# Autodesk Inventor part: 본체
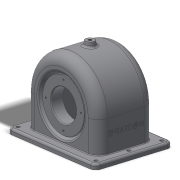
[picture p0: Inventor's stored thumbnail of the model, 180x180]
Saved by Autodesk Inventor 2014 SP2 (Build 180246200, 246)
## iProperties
Created: 2015-09
Part Number: 본체
Material: 일반
Document SubType Name: Modeling
Designer: 201-20
Density: 1 g/cm^3
Appearance: 기본값
Author: 201-20
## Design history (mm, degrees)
sketch "스케치6"
  geometry: L1 (-70, -40)-(70, -40); L2 (70, -40)-(70, -47); L3 (70, -47)-(-70, -47); L4 (-70, -47)-(-70, -40); 2 further points
  constraints: 8 end point, 2 parallel, 1 horizontal, 1 midpoint, 1 perpendicular, 1 vertical alignment
  dimensions: "d2" = 140 distance of L2.end L3.end; "d3" = 7 distance between parallel lines of L1 L3; "d4" = 47 distance from line of L3 point (0, 0)
extrude "돌출2" new body sketch "스케치6" stored distance "d5" = 104; taper "d6" = 0 deg
sketch "스케치10"
  geometry: L1 (70, -40)-(-70, -40) reference; L2 (-57, 0)-(57, 0); L3 (57, 0)-(57, -40); L4 (-57, -40)-(-57, 0); L5 (70, -47)-(-70, -47) reference; L6 (-51, 0)-(-51, -40); L7 (51, 0)-(51, -40); L8 (57, -40)-(51, -40); L9 (-51, -40)-(-57, -40); L10 (-51, -40)-(51, -40); A1 r 57 centre (0, 0) between (57, 0) and (-57, 0); A2 r 51 centre (0, 0) between (51, 0) and (-51, 0); 2 further points
  constraints: 16 end point, 5 perpendicular, 4 parallel, 4 point on circle, 3 midpoint, 2 centre point, 2 tangent, 1 coincident, 1 horizontal, 1 point on line, 1 vertical alignment
  dimensions: "d20" = 47 distance between parallel lines of L2 L5; "d21" = 6 radial gap between concentric circles of A1 A2; "d110" = 51 radius of A2
extrude "돌출3" join sketch "스케치10" stored distance "d17" = 77; taper "d18" = 0 deg
extrude "돌출4" cut sketch "스케치10" stored distance "d22" = 67; taper "d23" = 0 deg
sketch "스케치14"
  geometry: L1 (19, -18.5)-(121, -18.5); L2 (121, -18.5)-(121, -85.5); L3 (121, -85.5)-(19, -85.5); L4 (19, -85.5)-(19, -18.5); 3 further points
  constraints: 8 end point, 2 midpoint, 2 parallel, 1 horizontal, 1 horizontal alignment, 1 perpendicular, 1 vertical alignment
  dimensions: "d24" = 67 distance of L1.end L2.end; "d25" = 102 distance of L1.start L1.end
extrude "돌출5" cut sketch "스케치14" distance "d26" = 20; taper "d27" = 0 deg
fillet "모깎기1" dims "d28" = 14
fillet "모깎기3" dims "d34" = 9
sketch "스케치15"
  geometry: L1 (57, 38.5)-(0, 38.5) reference; L2 (51, 33.5)-(0, 33.5) reference; L3 (39.747, 33.5)-(28, 19.5); L4 (28, 19.5)-(20, 19.5); L5 (20, 19.5)-(20, 35.5); L6 (33, 33.237)-(37.416, 38.5); L7 (33, 33.237)-(33, 35.5); L8 (33, 35.5)-(20, 35.5); L9 (37.416, 38.5)-(39.747, 33.5); L10 (37.416, 38.5)-(20, 38.5); L11 (20, 38.5)-(20, 35.5); L12 (0, -72.8)-(0, 72.8) reference; 1 further point
  constraints: 18 end point, 3 parallel, 3 perpendicular, 3 point on line
  dimensions: "d30" = 28 horizontal distance of L3.end point (0, 0); "d31" = 3 distance between parallel lines of L8 L1; "d32" = 16 distance of L4.end L5.end; "d33" = 50 deg angle of L4 L3; "d35" = 33 distance from line of L7 point (0, 0); "d37" = 5 distance between parallel lines of L3 L6; "d38" = 20 distance from line of L5 point (0, 0)
revolve "회전1" stored, may be unused: angle "d39" = 90 deg
revolve "회전2" stored, may be unused: angle "d40" = 90 deg
sketch "스케치17"
  geometry: C1 r 31 at (0, 0); C2 r 20 at (0, 0); 1 further point
  constraints: 2 centre point, 2 coincident
  dimensions: "d41" = 62 diameter of C1; "d42" = 40 diameter of C2
extrude "돌출6" join sketch "스케치17" distance "d43" = 10; taper "d44" = 0 deg
sketch "스케치18"
  geometry: C1 r 20 at (0, 0) reference; 1 further point
extrude "돌출7" cut sketch "스케치18" distance "d45" = 87; taper "d46" = 0 deg
node "작업 평면2"
sketch "스케치20"
  geometry: C1 r 6 at (70, -52); 1 further point
  constraints: 1 centre point, 1 coincident
  dimensions: "d48" = 12 diameter of C1
extrude "돌출8" join sketch "스케치20" stored distance "d49" = 7; taper "d50" = 10 deg
hole "구멍1" diameter "d53" = 4.459; stored, may be unused: countersink angle "d57" = 90 deg, drill point angle "d59" = 0 deg; dims "d54" = 30, "d55" = 4, "d56" = 2, "d58" = 30, "d60" = 10, "d61" = 10
fillet "모깎기4" dims "d62" = 7
sketch "스케치21"
  geometry: 2 further points
  dimensions: "d63" = 62 horizontal distance of point (1, 8) point (63, 52); "d64" = 44 vertical distance of point (1, 8) point (63, 52)
hole "구멍2" sketch "스케치21" at (1, 8) diameter "d65" = 5; stored, may be unused: countersink angle "d69" = 90 deg, drill point angle "d71" = 0 deg; dims "d66" = 10, "d67" = 4, "d68" = 2, "d70" = 10
fillet "모깎기5" dims "d75" = 3, "d76" = 3, "d77" = 3, "d78" = 1
sketch "스케치22"
  geometry: 2 further points
  constraints: 1 vertical alignment
  dimensions: "d79" = 28 distance of point (0, 28) point (0, 0)
hole "구멍3" sketch "스케치22" at (0, 28) diameter "d80" = 2.459; stored, may be unused: countersink angle "d84" = 90 deg, drill point angle "d86" = 118 deg; dims "d81" = 7, "d82" = 4, "d83" = 2, "d85" = 9
chamfer "모따기1" distance "d90" = 1; stored, may be unused: second distance "d91" = 2, angle "d92" = 45 deg
fillet "모깎기6" dims "d93" = 0.5
sketch "스케치23"
  geometry: 2 further points
  constraints: 1 vertical alignment
  dimensions: "d94" = 24 distance of point (0, 24) point (0, 0)
hole "구멍4" sketch "스케치23" at (0, 24) diameter "d95" = 2.459; stored, may be unused: countersink angle "d99" = 90 deg, drill point angle "d101" = 118 deg; dims "d96" = 6, "d97" = 4, "d98" = 2, "d100" = 8
sketch "스케치24"
  geometry: L1 (-14, 0)-(-14, -39) reference; L2 (49, 0)-(0, 0) reference; L3 (-20.5, -47)-(69.5, -47) reference; 1 further point
  constraints: 1 other
  dimensions: "d108" = 38.5 distance from line of L1 point (24.5, -17); "d109" = 30 distance from line of point (24.5, -17) L3
feature "엠보싱1" sketch "스케치24" dims "d2" = 140, "d3" = 7, "d4" = 47, "d20" = 47, "d21" = 6, "d106" = 0.5, "d107" = 0, "d110" = 51
node "솔리드2"
pattern_linear "직사각형 패턴1" dims "d74" = 44
mirror "대칭1"
pattern_circular "원형 패턴1" dims angle "d88" = 360 deg
pattern_circular "원형 패턴2" dims angle "d103" = 360 deg
node "투영된 루프2"
